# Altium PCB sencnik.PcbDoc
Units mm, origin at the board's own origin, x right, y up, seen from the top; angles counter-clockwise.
Board outline 30 x 30 mm, 2 copper layers (Top Layer, Bottom Layer); 0 components, 0 nets, 13 pads, 0 vias.
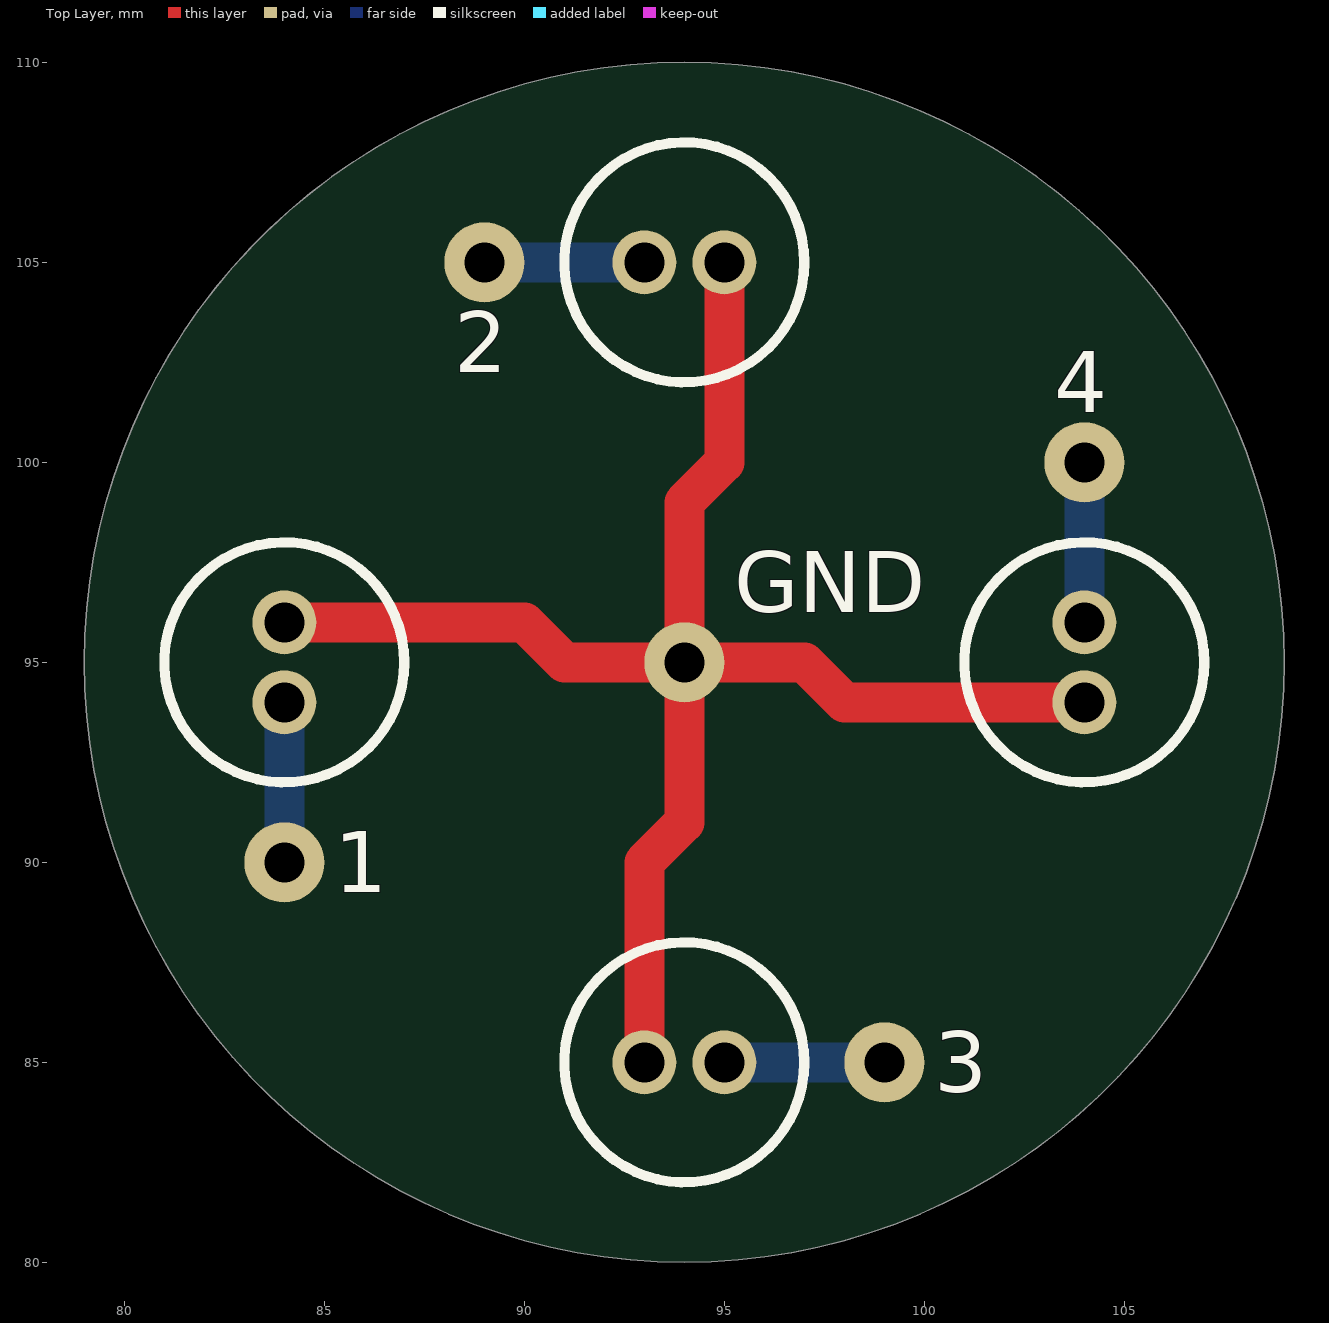
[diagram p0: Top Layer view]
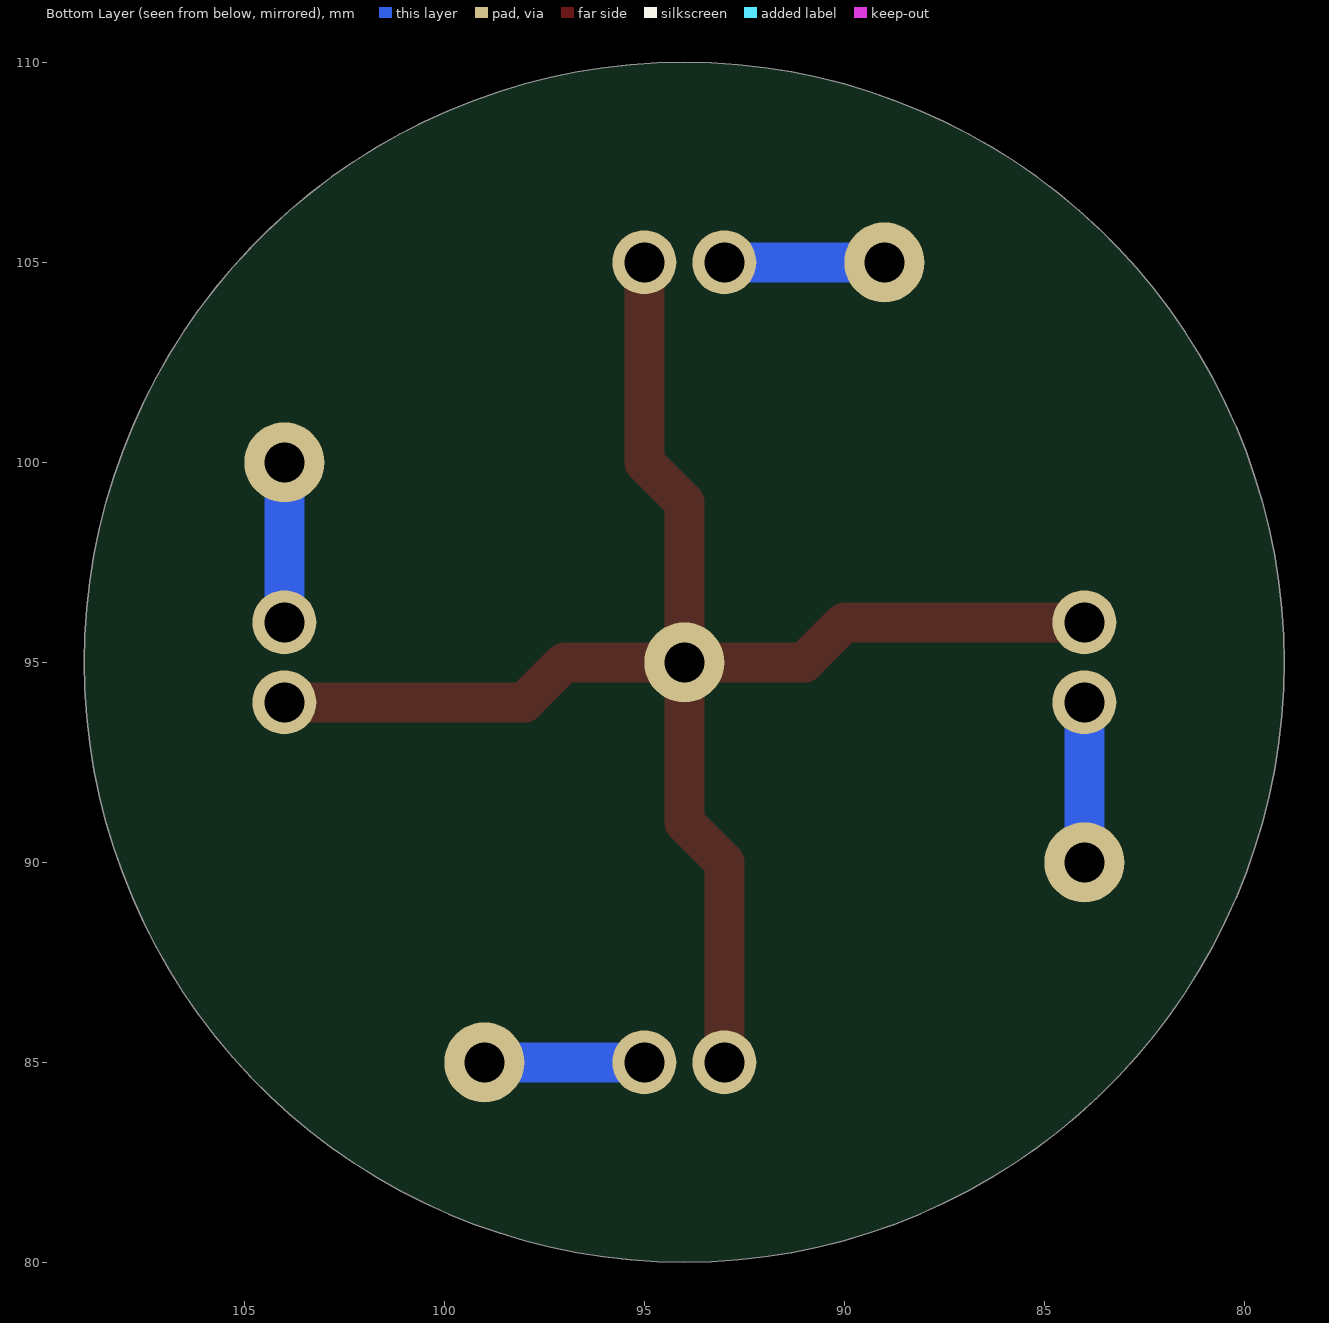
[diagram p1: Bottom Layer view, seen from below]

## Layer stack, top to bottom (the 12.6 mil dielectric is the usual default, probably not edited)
Top Solder: solder mask 0.0102, Solder Resist, Dk 3.5
Top Layer: signal copper 0.0356
Dielectric 1: dielectric 0.32, FR-4, Dk 4.8
Bottom Layer: signal copper 0.0356
Bottom Solder: solder mask 0.0102, Solder Resist, Dk 3.5

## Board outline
94,80 cw(c94,95) 79,95 cw(c94,95) 94,110 cw(c94,95) 109,95 cw(c94,95)

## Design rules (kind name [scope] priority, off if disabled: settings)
Clearance [All] p1: gap=0.254 ignorepadtopadclearanceinfootprint=FALSE except(0: Arc-Hole Track-Hole SMDPad-Hole THPad-Hole Via-Hole Fill-Hole Poly-Hole Region-Hole Text-Hole)
PolygonConnect [All] p1: connectstyle=Relief reliefconductorwidth=0.254 reliefentries=4 polygonreliefangle="90 Angle" airgapwidth=0.254
RoutingVias [All] p1: holewidth=0.711 width=1.27 viastyle="Through Hole" minholewidth=0.711 minwidth=1.27 maxholewidth=0.711 maxwidth=1.27
SolderMaskExpansion [All] p1: expansion=0.102 istentingtop=FALSE
Width [All] p1: maxlimit=2 minlimit=1 preferedwidth=1.5
30 further rules are at their usual default settings.

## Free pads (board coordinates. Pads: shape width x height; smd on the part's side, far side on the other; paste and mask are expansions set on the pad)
  round 2 hole 1: 173(84,90) 173(89,105) 173(94,95) 173(99,85) 173(104,100)
  round 1.6 hole 1: 173(93,105) 174(95,105) 175(104,96) 176(104,94) 177(93,85) 178(95,85) 179(84,96) 180(84,94)

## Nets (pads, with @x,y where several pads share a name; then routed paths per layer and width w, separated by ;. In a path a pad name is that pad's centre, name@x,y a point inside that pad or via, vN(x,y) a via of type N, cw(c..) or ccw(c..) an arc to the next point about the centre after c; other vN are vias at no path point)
copper on no net: | length 57.7
  Top Layer w1: 84,96 90,96 91,95 94,95 ; 93,85 93,90 94,91 94,95 ; 95,105 95,100 94,99 94,95 ; 104,94 98,94 97,95 94,95
  Bottom Layer w1: 84,90 84,94 ; 89,105 93,105 ; 95,85 99,85 ; 104,96 104,100

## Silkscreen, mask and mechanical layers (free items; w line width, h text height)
Top Overlay:
  circle w0.254: c84,95 r3
  circle w0.254: c94,85 r3
  circle w0.254: c104,95 r3
  circle w0.254: c94,105 r3
  text "2" at 88.254,102.254 h1.52
  text "4" at 103.254,101.254 h1.52
  text "GND" at 95.254,96.254 h1.52
  text "1" at 85.254,89.254 h1.52
  text "3" at 100.254,84.254 h1.52
Mechanical 1:
  circle w0.254: c94,95 r15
